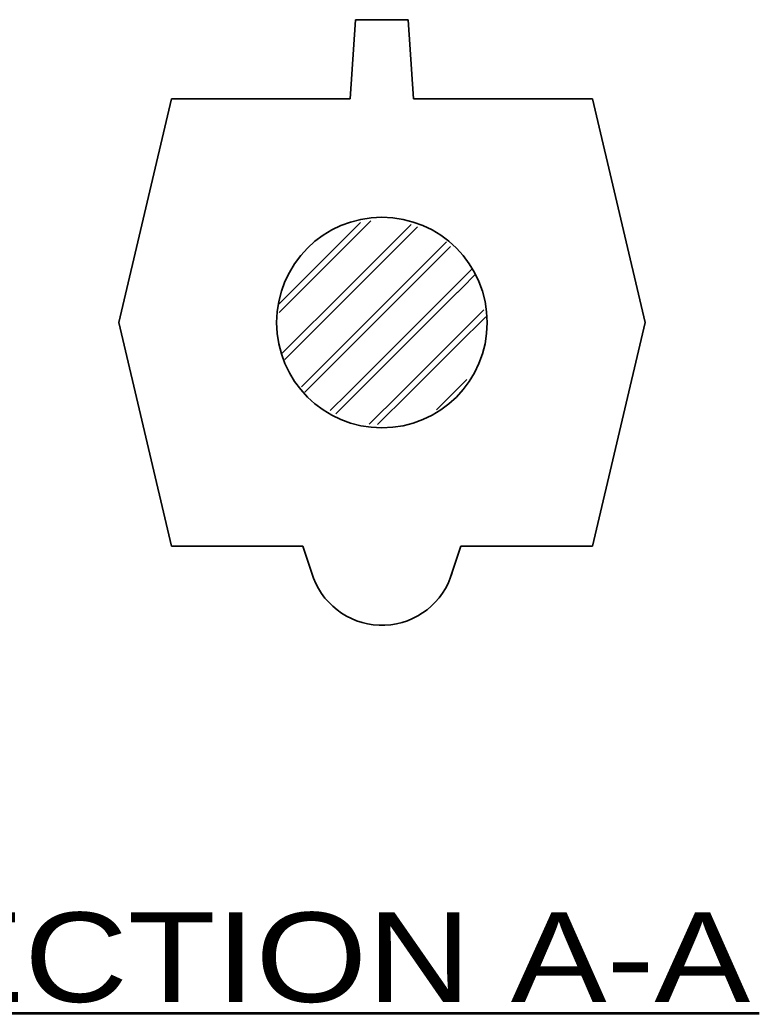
# Model space of a CAD drawing. Extents: x 15 to 140, y -57 to 117.
# Drawn here: x 123.6 to 137.65, y 7.42 to 26.28 of the extents above; entities that cross this region are included whole.
import ezdxf
from ezdxf.enums import TextEntityAlignment as Align

# ---------------------------------------------------------------- set-up
doc = ezdxf.new("R2010")
doc.units = 0
doc.header["$LTSCALE"] = 0.41
for name, color, linetype, lineweight in [('1', 7, 'Continuous', 35), ('12', 7, 'Continuous', 53), ('6', 7, 'Continuous', 13)]:
    doc.layers.add(name, color=color, linetype=linetype, lineweight=lineweight)

msp = doc.modelspace()

# ---------------------------------------------------------------- linework, layer by layer
at = {"layer": '1'}
for p, q in [((129.9796, 26.2833), (129.8796, 24.7833)), ((129.9796, 26.2833), (130.9796, 26.2833)), ((130.9796, 26.2833), (131.0796, 24.7833)), ((126.4796, 24.7833), (129.8796, 24.7833)), ((131.0796, 24.7833), (134.4796, 24.7833)), ((126.4796, 16.2833), (128.9796, 16.2833)), ((128.9796, 16.2833), (129.1809, 15.6793)), ((131.9796, 16.2833), (131.7785, 15.6802)), ((131.9796, 16.2833), (134.4796, 16.2833))]:
    msp.add_line(p, q, dxfattribs=at)
for points in [[(126.4796, 24.7833), (125.4796, 20.5333), (126.4796, 16.2833)], [(134.4796, 24.7833), (135.4796, 20.5333), (134.4796, 16.2833)]]:
    msp.add_lwpolyline(points, dxfattribs=at)
msp.add_circle((130.4796, 20.5333), 2, dxfattribs=at)
msp.add_arc((130.4795, 16.1724), 1.3891, 200.79114, 343.88139, dxfattribs=at)
at = {"layer": '12'}
msp.add_line((119.8744, 7.4159), (137.6453, 7.4159), dxfattribs=at)
at = {"layer": '6'}
for p, q in [((128.9981, 21.1943), (130.2669, 22.4631)), ((128.8315, 21.1943), (130.0708, 22.4337)), ((129.8315, 21.1943), (131.0328, 22.3957)), ((129.9981, 21.1943), (131.1556, 22.3518)), ((130.8315, 21.1943), (131.7059, 22.0687)), ((130.9981, 21.1943), (131.7852, 21.9814)), ((131.9185, 21.2777), (132.1834, 21.5426)), ((132.0018, 21.1943), (132.2513, 21.4438)), ((128.5189, 20.8818), (128.8315, 21.1943)), ((128.5271, 20.7234), (128.9981, 21.1943)), ((128.5738, 19.9366), (129.8315, 21.1943)), ((128.6365, 19.8327), (129.9981, 21.1943)), ((128.9501, 19.313), (130.8315, 21.1943)), ((129.0129, 19.2091), (130.9981, 21.1943)), ((129.8315, 19.1943), (131.8315, 21.1943)), ((131.8315, 21.1943), (131.9148, 21.2777)), ((132.0018, 21.1943), (131.9148, 21.1073)), ((129.9981, 19.1943), (131.9148, 21.111)), ((131.9185, 20.2777), (132.4183, 20.7775)), ((132.4517, 20.6443), (131.9185, 20.111)), ((130.8315, 19.1943), (131.9148, 20.2777)), ((130.9981, 19.1943), (131.9148, 20.111)), ((131.9185, 19.2777), (132.0911, 19.4503)), ((131.8315, 19.1943), (131.9148, 19.2777)), ((129.4974, 18.8603), (129.8315, 19.1943)), ((129.6019, 18.7981), (129.9981, 19.1943)), ((130.2394, 18.6022), (130.8315, 19.1943)), ((130.3988, 18.595), (130.9981, 19.1943)), ((131.5154, 18.8783), (131.8315, 19.1943))]:
    msp.add_line(p, q, dxfattribs=at)

# ---------------------------------------------------------------- texts
at = {"layer": '12', "width": 1.2}
msp.add_text('SECTION A-A', height=1.7, dxfattribs=at).set_placement((128.7598, 7.6284), align=Align.CENTER)

doc.saveas('drawing.dxf')
